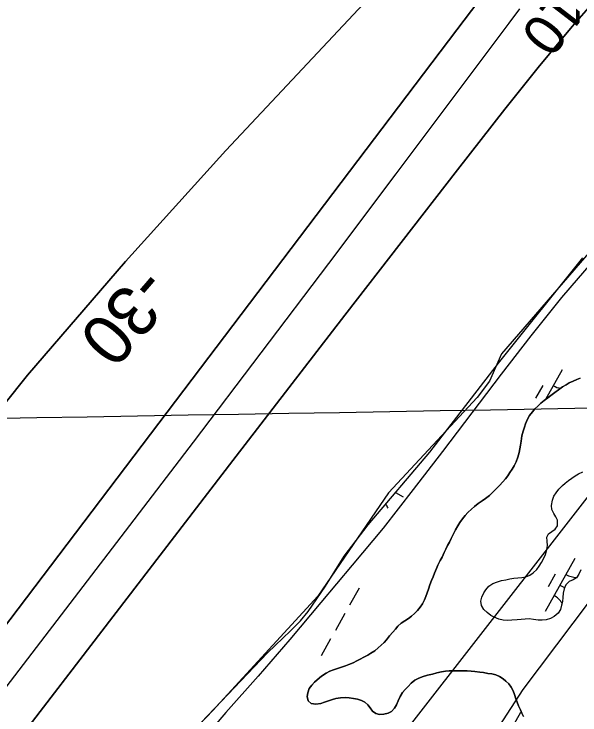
# Model space of a CAD drawing. Extents: x 3913936 to 3933962, y 195330 to 217741.
# Drawn here: x 3922187 to 3922654, y 199333 to 199912 of the extents above; entities that cross this region are included whole.
import ezdxf

# ---------------------------------------------------------------- set-up
doc = ezdxf.new("R2010")
doc.units = 0
for name, color, linetype in [('V-GRID-MAJR', 7, 'Continuous'), ('V-RIVR-EDGE', 7, 'Continuous'), ('V-RIVR-RANG', 7, 'Continuous'), ('V-RRAP-FSHR', 7, 'Continuous'), ('V-TOPO-DPTH', 7, 'Continuous'), ('V-TOPO-MINR', 7, 'Continuous'), ('V-TOPO-MINR-IDEN', 7, 'Continuous'), ('V-TOPO-SHOR', 7, 'Continuous'), ('V-UTIL-LINE', 7, 'Continuous'), ('V-WETL-SWMP', 7, 'Continuous')]:
    doc.layers.add(name, color=color, linetype=linetype)

msp = doc.modelspace()

# ---------------------------------------------------------------- linework, layer by layer
at = {"layer": 'V-GRID-MAJR'}
msp.add_spline([(3918580.26, 199515.41), (3920000.19, 199540.18), (3925326.04, 199633.54), (3926654.92, 199656.95)], degree=3, dxfattribs=at)
at = {"layer": 'V-RIVR-EDGE'}
msp.add_lwpolyline([(3922915.85, 200002.09), (3922760.82, 199830.21), (3922588.94, 199631.37), (3922578.83, 199608.9), (3922568.72, 199595.42), (3922495.7, 199516.78), (3922437.28, 199431.4), (3922350.78, 199337.04), (3922232.82, 199213.46), (3922129.47, 199055.06)], dxfattribs=at)
at = {"layer": 'V-RRAP-FSHR'}
msp.add_lwpolyline([(3922856.72, 199910.69), (3922828.81, 199882.43), (3922800.8, 199853.48), (3922772.41, 199825.3), (3922744.18, 199797.13), (3922715.63, 199768.95), (3922689.57, 199738.64), (3922664.23, 199707.86), (3922638.48, 199677.79), (3922612.93, 199646.3), (3922588.47, 199614.66), (3922564.3, 199582.79), (3922540.12, 199550.92), (3922515.95, 199519.51), (3922491.29, 199487.57), (3922465.58, 199456.93), (3922439.87, 199426.28), (3922414.17, 199395.64), (3922387.94, 199365.43), (3922361.51, 199335.42), (3922335.68, 199305.4)], dxfattribs=at)
at = {"layer": 'V-TOPO-DPTH'}
for points in [[(3923572.36, 200998.52), (3923503.91, 200907.2), (3923435.27, 200816.03), (3923326.2, 200671.67), (3923311.77, 200652.93), (3923297.12, 200634.37), (3923282.13, 200616.08), (3923266.93, 200597.97), (3923166.97, 200481.11), (3923101.22, 200405.05), (3923034.94, 200329.46), (3922967.87, 200254.57), (3922900.28, 200180.15), (3922705.27, 199967.65), (3922675.93, 199934.9), (3922647.14, 199901.69), (3922619.17, 199867.8), (3922591.73, 199833.44), (3922552.62, 199783.23), (3922506.1, 199723.37), (3922459.66, 199663.45), (3922413.34, 199603.44), (3922367.1, 199543.37), (3922084.4, 199175.27)], [(3922148.48, 199366.57), (3922552.04, 199898.75), (3922570.26, 199922.71), (3922588.51, 199946.64), (3922606.81, 199970.53), (3922625.15, 199994.39), (3922688.22, 200076.25), (3922736.83, 200138.24), (3922786.12, 200199.67), (3922836.45, 200260.25), (3922887.47, 200320.27), (3922938.76, 200380.07), (3922989.72, 200440.16), (3923040.17, 200500.67), (3923090.29, 200561.46), (3923185.73, 200678.2), (3923195.93, 200690.87), (3923206, 200703.64), (3923215.88, 200716.57), (3923225.63, 200729.59), (3923304.51, 200836.62), (3923353.97, 200902.94), (3923403.94, 200968.88)], [(3923403.94, 200968.88), (3923353.97, 200902.94), (3923304.51, 200836.62), (3923225.63, 200729.59), (3923215.88, 200716.57), (3923206, 200703.64), (3923195.93, 200690.87), (3923185.73, 200678.2), (3923090.29, 200561.46), (3923040.17, 200500.67), (3922989.72, 200440.16), (3922938.76, 200380.07), (3922887.47, 200320.27), (3922836.45, 200260.25), (3922786.12, 200199.67), (3922736.83, 200138.24), (3922688.22, 200076.25), (3922625.15, 199994.39), (3922606.81, 199970.53), (3922588.51, 199946.64), (3922570.26, 199922.71), (3922552.04, 199898.75), (3922148.48, 199366.57)], [(3922120.56, 199517.31), (3922197.86, 199613.84), (3922278.57, 199707.54), (3922361.53, 199799.36), (3922529.74, 199978.99)], [(3922529.74, 199978.99), (3922361.53, 199799.36), (3922278.57, 199707.54), (3922197.86, 199613.84), (3922120.56, 199517.31)]]:
    msp.add_lwpolyline(points, dxfattribs=at)
at = {"layer": 'V-TOPO-MINR'}
for points in [[(3922084.4, 199175.27), (3922367.1, 199543.37), (3922413.34, 199603.44), (3922459.66, 199663.45), (3922506.1, 199723.37), (3922552.62, 199783.23), (3922591.73, 199833.44), (3922619.17, 199867.8), (3922647.14, 199901.69), (3922675.93, 199934.9), (3922705.27, 199967.65), (3922900.28, 200180.15), (3922967.87, 200254.57), (3923034.94, 200329.46), (3923101.22, 200405.05), (3923166.97, 200481.11), (3923266.93, 200597.97), (3923282.13, 200616.08), (3923297.12, 200634.37), (3923311.77, 200652.93), (3923326.2, 200671.67), (3923435.27, 200816.03), (3923503.91, 200907.2), (3923572.36, 200998.52)], [(3922148.48, 199366.57), (3922552.04, 199898.75), (3922570.26, 199922.71), (3922588.51, 199946.64), (3922606.81, 199970.53), (3922625.15, 199994.39), (3922688.22, 200076.25), (3922736.83, 200138.24), (3922786.12, 200199.67), (3922836.45, 200260.25), (3922887.47, 200320.27), (3922938.76, 200380.07), (3922989.72, 200440.16), (3923040.17, 200500.67), (3923090.29, 200561.46), (3923185.73, 200678.2), (3923195.93, 200690.87), (3923206, 200703.64), (3923215.88, 200716.57), (3923225.63, 200729.59), (3923304.51, 200836.62), (3923353.97, 200902.94), (3923403.94, 200968.88)], [(3922120.56, 199517.31), (3922197.86, 199613.84), (3922278.57, 199707.54), (3922361.53, 199799.36), (3922529.74, 199978.99)], [(3922036.49, 199168.9), (3922278.56, 199485.01), (3922334.68, 199558.54), (3922390.63, 199632.19), (3922446.35, 199706.03), (3922501.91, 199779.98), (3922595.1, 199904.45), (3922603.96, 199916.25)]]:
    msp.add_lwpolyline(points, dxfattribs=at)
at = {"layer": 'V-TOPO-SHOR'}
for points in [[(3922523.75, 199425.15), (3922525.3, 199428.35), (3922526.41, 199431.21), (3922527.53, 199434.16), (3922528.56, 199437.1), (3922529.85, 199440.65), (3922531.14, 199444.2), (3922532.34, 199447.32), (3922533.46, 199450.26), (3922535.18, 199454.08), (3922536.46, 199457.02), (3922538.36, 199460.92), (3922539.82, 199463.69), (3922541.46, 199467.33), (3922542.92, 199470.1), (3922544.38, 199473.31), (3922545.84, 199475.99), (3922547.3, 199478.94), (3922549.03, 199482.23), (3922551, 199486.05), (3922552.81, 199489.34), (3922554.54, 199492.29), (3922556.69, 199495.23), (3922558.85, 199498.01), (3922561.17, 199500.52), (3922564.02, 199503.21), (3922566.61, 199505.47), (3922569.72, 199507.82), (3922572.83, 199509.99), (3922575.76, 199512.07), (3922578.87, 199514.59), (3922581.81, 199517.19), (3922584.57, 199519.97), (3922587.15, 199522.66), (3922590, 199525.78), (3922592.07, 199528.3), (3922594.05, 199530.81), (3922595.86, 199533.41), (3922597.67, 199536.18), (3922599.4, 199539.05), (3922600.94, 199542.25), (3922602.4, 199546.15), (3922603.43, 199549.87), (3922604.03, 199552.99), (3922604.54, 199556.11), (3922605.14, 199559.39), (3922605.73, 199563.63), (3922606.75, 199567.62), (3922607.7, 199570.82), (3922608.64, 199573.68), (3922610.28, 199577.4), (3922612.08, 199580.44), (3922614.33, 199583.56), (3922616.4, 199585.99), (3922618.81, 199588.33), (3922621.4, 199590.76), (3922624.16, 199592.93), (3922627.1, 199595.1), (3922629.52, 199597.1), (3922632.88, 199599.62), (3922635.91, 199601.7), (3922639.27, 199604.05), (3922642.12, 199605.78), (3922644.71, 199607.35), (3922648.08, 199608.92), (3922650.94, 199610.14), (3922653.79, 199611.27)], [(3922635.02, 199493.99), (3922633.81, 199496.75), (3922632.16, 199499.69), (3922630.51, 199502.79), (3922630.07, 199506.33), (3922630.92, 199510.57), (3922632.12, 199513.95), (3922634.01, 199516.8), (3922636.25, 199519.66), (3922639.18, 199522.61), (3922641.51, 199524.69), (3922644.09, 199526.85), (3922646.85, 199528.76), (3922649.53, 199530.58), (3922652.37, 199532.49), (3922655.91, 199534.06)], [(3922615.1, 199450.56), (3922618.03, 199453.42), (3922620.01, 199456.27), (3922621.81, 199459.22), (3922623.45, 199462.16), (3922625.17, 199465.79), (3922626.28, 199469.77), (3922626.7, 199473.14), (3922626.43, 199476.86), (3922626.34, 199480.05), (3922627.71, 199482.91), (3922630.3, 199484.65), (3922633.23, 199486.73), (3922635.04, 199489.41), (3922635.02, 199493.99)], [(3922654.24, 199453.17), (3922652.78, 199449.54), (3922650.8, 199446.51), (3922647.87, 199444.86), (3922644.67, 199443.55), (3922641.91, 199440.69), (3922640.45, 199437.49), (3922639.77, 199433.95), (3922639.44, 199430.23), (3922639.1, 199426.95), (3922638.5, 199423.92), (3922637.48, 199420.38), (3922635.58, 199417.26), (3922632.31, 199414.49), (3922629.29, 199412.83), (3922625.75, 199411.79), (3922622.38, 199411.52), (3922619.18, 199411.68), (3922615.29, 199412.19), (3922611.75, 199412.7), (3922608.29, 199412.52), (3922605.01, 199412.16), (3922601.73, 199411.72), (3922597.41, 199411.54), (3922594.21, 199411.27), (3922590.15, 199411.69), (3922586.69, 199412.37), (3922582.8, 199414), (3922580.03, 199415.38), (3922576.91, 199417.87), (3922574.4, 199420.37), (3922572.31, 199423.56), (3922571.87, 199427.28), (3922572.73, 199430.48), (3922574.36, 199434.03), (3922575.99, 199436.71), (3922578.32, 199439.65), (3922581.59, 199441.91), (3922585.48, 199443.21), (3922588.85, 199444.26), (3922592.56, 199444.96), (3922595.67, 199445.66), (3922598.95, 199446.11), (3922602.23, 199446.55), (3922605.6, 199446.82), (3922608.89, 199447.43), (3922612.25, 199448.73), (3922615.1, 199450.56)], [(3922607.07, 199331.94), (3922605.76, 199334.7), (3922604.46, 199337.64), (3922602.98, 199340.75), (3922601.76, 199343.78), (3922600.8, 199346.71), (3922599.49, 199350.17), (3922598.36, 199353.11), (3922596.88, 199356.22), (3922594.79, 199359.07), (3922592.45, 199361.23), (3922590.11, 199363.12), (3922587.07, 199365.1), (3922584.13, 199366.4), (3922580.84, 199367.17), (3922577.64, 199367.67), (3922574.09, 199368.27), (3922571.06, 199368.69), (3922566.91, 199369.29), (3922563.79, 199369.54), (3922560.41, 199369.7), (3922556.35, 199369.78), (3922552.54, 199369.68), (3922549.25, 199369.76), (3922545.71, 199369.66), (3922542.59, 199369.4), (3922539.22, 199368.86), (3922535.42, 199368.08), (3922531.96, 199367.11), (3922527.72, 199366.07), (3922523.4, 199364.75), (3922520.03, 199363.53), (3922517.26, 199362.06), (3922514.33, 199359.63), (3922511.74, 199356.94), (3922509.24, 199354.33), (3922507.08, 199351.82), (3922505.19, 199348.61), (3922503.55, 199345.06), (3922502.18, 199341.77), (3922500.46, 199338.82), (3922498.13, 199336.13), (3922495.27, 199334.83), (3922491.82, 199334.04), (3922488.18, 199333.77), (3922485.15, 199334.45), (3922482.29, 199336.43), (3922480.47, 199339.2), (3922478.56, 199341.7), (3922476.04, 199343.94), (3922473.36, 199345.32), (3922470.15, 199346.27), (3922466.86, 199346.86), (3922463.06, 199347.37), (3922459.77, 199347.62), (3922455.96, 199347.35), (3922452.24, 199346.91), (3922449.3, 199346.12), (3922446.1, 199345.07), (3922442.91, 199343.77), (3922439.79, 199342.81), (3922435.73, 199342.19), (3922431.83, 199342.78), (3922429.41, 199344.94), (3922428.53, 199348.49), (3922428.95, 199351.69), (3922430.24, 199355.15), (3922432.31, 199358.01), (3922434.55, 199360.27), (3922436.88, 199362.44), (3922440.34, 199365.21), (3922444.31, 199367.74), (3922447.25, 199369.39), (3922450.27, 199370.52), (3922453.56, 199371.66), (3922456.84, 199372.79), (3922460.13, 199373.84), (3922462.98, 199374.97), (3922466.35, 199376.45), (3922469.37, 199378.01), (3922472.31, 199379.41), (3922475.25, 199380.89), (3922478.44, 199382.63), (3922481.12, 199384.28), (3922484.32, 199386.28), (3922487.08, 199388.71), (3922489.67, 199391.05), (3922491.91, 199393.13), (3922494.07, 199395.47), (3922496.57, 199398.51), (3922499.16, 199401.54), (3922501.31, 199404.15), (3922503.29, 199406.49), (3922505.97, 199409.01), (3922508.99, 199410.92), (3922512.19, 199413), (3922514.52, 199414.91), (3922517.19, 199417.17), (3922519.44, 199419.51), (3922521.77, 199422.29), (3922523.75, 199425.15)]]:
    msp.add_lwpolyline(points, dxfattribs=at)
at = {"layer": 'V-UTIL-LINE'}
for points in [[(3922166.91, 198676.44), (3922606.64, 199354.27), (3923719.03, 200830.83), (3923718.13, 200956.52)], [(3922951.57, 199888.34), (3922069.47, 198754.87)]]:
    msp.add_lwpolyline(points, dxfattribs=at)
at = {"layer": 'V-WETL-SWMP'}
for p, q in [((3922586.49, 199623.64), (3922655.96, 199710.58)), ((3922529.77, 199550.29), (3922586.49, 199623.64)), ((3922638.9, 199618.16), (3922625.11, 199593.63)), ((3922648.08, 199608.92), (3922644.71, 199607.35)), ((3922650.94, 199610.14), (3922648.08, 199608.92)), ((3922653.79, 199611.27), (3922650.94, 199610.14)), ((3922622.87, 199605.38), (3922616.99, 199594.92)), ((3922639.27, 199604.05), (3922635.91, 199601.7)), ((3922642.12, 199605.78), (3922639.27, 199604.05)), ((3922644.71, 199607.35), (3922642.12, 199605.78)), ((3922626.65, 199596.37), (3922627.83, 199595.71)), ((3922629.52, 199597.1), (3922627.1, 199595.1)), ((3922632.88, 199599.62), (3922629.52, 199597.1)), ((3922635.91, 199601.7), (3922632.88, 199599.62)), ((3922621.4, 199590.76), (3922618.81, 199588.33)), ((3922624.16, 199592.93), (3922621.4, 199590.76)), ((3922627.1, 199595.1), (3922624.16, 199592.93)), ((3922616.4, 199585.99), (3922614.33, 199583.56)), ((3922618.81, 199588.33), (3922616.4, 199585.99)), ((3922612.08, 199580.44), (3922610.28, 199577.4)), ((3922614.33, 199583.56), (3922612.08, 199580.44)), ((3922608.64, 199573.68), (3922607.7, 199570.82)), ((3922610.28, 199577.4), (3922608.64, 199573.68)), ((3922606.76, 199567.62), (3922605.73, 199563.63)), ((3922607.7, 199570.82), (3922606.76, 199567.62)), ((3922605.73, 199563.63), (3922605.14, 199559.39)), ((3922604.54, 199556.1), (3922604.03, 199552.99)), ((3922605.14, 199559.39), (3922604.54, 199556.1)), ((3922478.83, 199490.13), (3922529.77, 199550.29)), ((3922603.43, 199549.87), (3922602.4, 199546.15)), ((3922604.03, 199552.99), (3922603.43, 199549.87)), ((3922602.4, 199546.15), (3922600.94, 199542.25)), ((3922599.4, 199539.05), (3922597.67, 199536.18)), ((3922600.94, 199542.25), (3922599.4, 199539.05)), ((3922595.86, 199533.41), (3922594.05, 199530.81)), ((3922597.67, 199536.18), (3922595.86, 199533.41)), ((3922592.07, 199528.3), (3922590, 199525.78)), ((3922594.05, 199530.81), (3922592.07, 199528.3)), ((3922587.16, 199522.66), (3922584.57, 199519.97)), ((3922590, 199525.78), (3922587.16, 199522.66)), ((3922501.42, 199516.81), (3922507.74, 199513.26)), ((3922581.81, 199517.19), (3922578.87, 199514.59)), ((3922584.57, 199519.97), (3922581.81, 199517.19)), ((3922572.83, 199509.99), (3922569.72, 199507.82)), ((3922575.76, 199512.07), (3922572.83, 199509.99)), ((3922578.87, 199514.59), (3922575.76, 199512.07)), ((3922566.61, 199505.47), (3922564.02, 199503.21)), ((3922569.72, 199507.82), (3922566.61, 199505.47)), ((3922558.85, 199498.01), (3922556.69, 199495.23)), ((3922561.17, 199500.52), (3922558.85, 199498.01)), ((3922564.02, 199503.21), (3922561.17, 199500.52)), ((3922554.54, 199492.29), (3922552.81, 199489.34)), ((3922556.69, 199495.23), (3922554.54, 199492.29)), ((3922459.15, 199464.51), (3922478.83, 199490.13)), ((3922551, 199486.05), (3922549.03, 199482.23)), ((3922552.81, 199489.34), (3922551, 199486.05)), ((3922549.03, 199482.23), (3922547.31, 199478.94)), ((3922545.84, 199476), (3922544.38, 199473.31)), ((3922547.31, 199478.94), (3922545.84, 199476)), ((3922542.92, 199470.1), (3922541.45, 199467.33)), ((3922544.38, 199473.31), (3922542.92, 199470.1)), ((3922443.73, 199439.69), (3922459.15, 199464.51)), ((3922539.82, 199463.69), (3922538.36, 199460.92)), ((3922541.45, 199467.33), (3922539.82, 199463.69)), ((3922538.36, 199460.92), (3922536.46, 199457.02)), ((3922649.3, 199462.37), (3922624.8, 199418.78)), ((3922535.18, 199454.08), (3922533.46, 199450.27)), ((3922536.46, 199457.02), (3922535.18, 199454.08)), ((3922532.34, 199447.32), (3922531.14, 199444.2)), ((3922533.46, 199450.27), (3922532.34, 199447.32)), ((3922633.26, 199449.58), (3922627.38, 199439.12)), ((3922529.85, 199440.65), (3922528.56, 199437.1)), ((3922531.14, 199444.2), (3922529.85, 199440.65)), ((3922637.05, 199440.57), (3922640.88, 199438.42)), ((3922429.46, 199418.74), (3922443.73, 199439.69)), ((3922471.35, 199437.89), (3922463.51, 199423.94)), ((3922527.53, 199434.16), (3922526.41, 199431.21)), ((3922528.56, 199437.1), (3922527.53, 199434.16)), ((3922525.3, 199428.35), (3922523.75, 199425.15)), ((3922526.41, 199431.21), (3922525.3, 199428.35)), ((3922523.75, 199425.15), (3922521.77, 199422.29)), ((3922422.9, 199410.97), (3922429.46, 199418.74)), ((3922459.59, 199416.97), (3922451.75, 199403.02)), ((3922517.2, 199417.17), (3922514.52, 199414.91)), ((3922519.44, 199419.51), (3922517.2, 199417.17)), ((3922521.77, 199422.29), (3922519.44, 199419.51)), ((3922414.79, 199402.82), (3922422.9, 199410.97)), ((3922508.99, 199410.92), (3922505.97, 199409.01)), ((3922512.19, 199413), (3922508.99, 199410.92)), ((3922514.52, 199414.91), (3922512.19, 199413)), ((3922503.29, 199406.49), (3922501.31, 199404.15)), ((3922505.97, 199409.01), (3922503.29, 199406.49)), ((3922395.86, 199384.57), (3922414.79, 199402.82)), ((3922499.16, 199401.55), (3922496.57, 199398.51)), ((3922501.31, 199404.15), (3922499.16, 199401.55)), ((3922447.83, 199396.05), (3922439.99, 199382.1)), ((3922494.07, 199395.47), (3922491.91, 199393.13)), ((3922496.57, 199398.51), (3922494.07, 199395.47)), ((3922487.08, 199388.71), (3922484.32, 199386.28)), ((3922489.67, 199391.05), (3922487.08, 199388.71)), ((3922491.91, 199393.13), (3922489.67, 199391.05)), ((3922341.03, 199327.1), (3922395.86, 199384.57)), ((3922478.44, 199382.63), (3922475.25, 199380.89)), ((3922481.12, 199384.28), (3922478.44, 199382.63)), ((3922484.32, 199386.28), (3922481.12, 199384.28)), ((3922466.35, 199376.45), (3922462.98, 199374.97)), ((3922469.37, 199378.01), (3922466.35, 199376.45)), ((3922472.31, 199379.41), (3922469.37, 199378.01)), ((3922475.25, 199380.89), (3922472.31, 199379.41)), ((3922450.27, 199370.52), (3922447.25, 199369.39)), ((3922453.56, 199371.65), (3922450.27, 199370.52)), ((3922456.84, 199372.79), (3922453.56, 199371.65)), ((3922460.13, 199373.84), (3922456.84, 199372.79)), ((3922462.98, 199374.97), (3922460.13, 199373.84)), ((3922440.34, 199365.21), (3922436.88, 199362.44)), ((3922444.31, 199367.74), (3922440.34, 199365.21)), ((3922447.25, 199369.39), (3922444.31, 199367.74)), ((3922520.03, 199363.53), (3922523.4, 199364.76)), ((3922523.4, 199364.76), (3922527.72, 199366.07)), ((3922527.72, 199366.07), (3922531.96, 199367.11)), ((3922531.96, 199367.11), (3922535.42, 199368.08)), ((3922535.42, 199368.08), (3922539.22, 199368.86)), ((3922539.22, 199368.86), (3922542.59, 199369.39)), ((3922542.59, 199369.39), (3922545.71, 199369.66)), ((3922545.71, 199369.66), (3922549.25, 199369.76)), ((3922549.25, 199369.76), (3922552.54, 199369.68)), ((3922552.54, 199369.68), (3922556.35, 199369.78)), ((3922556.35, 199369.78), (3922560.41, 199369.7)), ((3922560.41, 199369.7), (3922563.79, 199369.54)), ((3922563.79, 199369.54), (3922566.91, 199369.29)), ((3922566.91, 199369.29), (3922571.06, 199368.69)), ((3922571.06, 199368.69), (3922574.09, 199368.27)), ((3922574.09, 199368.27), (3922577.64, 199367.67)), ((3922577.64, 199367.67), (3922580.84, 199367.17)), ((3922580.84, 199367.17), (3922584.13, 199366.4)), ((3922584.13, 199366.4), (3922587.08, 199365.11)), ((3922587.08, 199365.11), (3922590.11, 199363.12)), ((3922434.55, 199360.27), (3922432.31, 199358.01)), ((3922436.88, 199362.44), (3922434.55, 199360.27)), ((3922511.74, 199356.94), (3922514.33, 199359.62)), ((3922514.33, 199359.62), (3922517.26, 199362.06)), ((3922517.26, 199362.06), (3922520.03, 199363.53)), ((3922590.11, 199363.12), (3922592.45, 199361.23)), ((3922592.45, 199361.23), (3922594.79, 199359.07)), ((3922594.79, 199359.07), (3922596.88, 199356.22)), ((3922430.24, 199355.15), (3922428.95, 199351.69)), ((3922432.31, 199358.01), (3922430.24, 199355.15)), ((3922507.08, 199351.82), (3922509.24, 199354.33)), ((3922509.24, 199354.33), (3922511.74, 199356.94)), ((3922596.88, 199356.22), (3922598.36, 199353.11)), ((3922598.36, 199353.11), (3922599.49, 199350.17)), ((3922428.95, 199351.69), (3922428.53, 199348.48)), ((3922428.53, 199348.48), (3922429.41, 199344.94)), ((3922452.24, 199346.91), (3922455.96, 199347.35)), ((3922455.96, 199347.35), (3922459.77, 199347.62)), ((3922459.77, 199347.62), (3922463.06, 199347.37)), ((3922463.06, 199347.37), (3922466.86, 199346.86)), ((3922503.55, 199345.06), (3922505.19, 199348.61)), ((3922505.19, 199348.61), (3922507.08, 199351.82)), ((3922599.49, 199350.17), (3922600.8, 199346.71)), ((3922429.41, 199344.94), (3922431.83, 199342.78)), ((3922431.83, 199342.78), (3922435.73, 199342.19)), ((3922435.73, 199342.19), (3922439.79, 199342.8)), ((3922439.79, 199342.8), (3922442.91, 199343.77)), ((3922442.91, 199343.77), (3922446.1, 199345.07)), ((3922446.1, 199345.07), (3922449.3, 199346.12)), ((3922449.3, 199346.12), (3922452.24, 199346.91)), ((3922466.86, 199346.86), (3922470.15, 199346.26)), ((3922470.15, 199346.26), (3922473.36, 199345.32)), ((3922473.36, 199345.32), (3922476.04, 199343.95)), ((3922476.04, 199343.95), (3922478.56, 199341.7)), ((3922478.56, 199341.7), (3922480.47, 199339.2)), ((3922500.46, 199338.82), (3922502.18, 199341.77)), ((3922502.18, 199341.77), (3922503.55, 199345.06)), ((3922600.8, 199346.71), (3922601.76, 199343.78)), ((3922601.76, 199343.78), (3922602.98, 199340.75)), ((3922480.47, 199339.2), (3922482.29, 199336.43)), ((3922482.29, 199336.43), (3922485.15, 199334.45)), ((3922495.27, 199334.83), (3922498.13, 199336.13)), ((3922498.13, 199336.13), (3922500.46, 199338.82)), ((3922602.98, 199340.75), (3922604.46, 199337.64)), ((3922604.46, 199337.64), (3922605.76, 199334.7)), ((3922485.15, 199334.45), (3922488.18, 199333.77)), ((3922488.18, 199333.77), (3922491.82, 199334.04)), ((3922491.82, 199334.04), (3922495.27, 199334.83)), ((3922604.59, 199335.46), (3922596.75, 199321.51)), ((3922605.76, 199334.7), (3922607.07, 199331.94))]:
    msp.add_line(p, q, dxfattribs=at)
for points in [[(3922615.1, 199450.56), (3922618.03, 199453.42), (3922620.01, 199456.27), (3922621.81, 199459.22), (3922623.45, 199462.16), (3922625.17, 199465.79), (3922626.28, 199469.77), (3922626.7, 199473.14), (3922626.43, 199476.86), (3922626.34, 199480.05), (3922627.71, 199482.91), (3922630.3, 199484.65), (3922633.23, 199486.73), (3922635.04, 199489.41), (3922635.02, 199493.99), (3922633.81, 199496.75), (3922632.16, 199499.69), (3922630.51, 199502.79), (3922630.06, 199506.33), (3922630.92, 199510.57), (3922632.12, 199513.95), (3922634.01, 199516.8), (3922636.25, 199519.66), (3922639.18, 199522.61), (3922641.51, 199524.69), (3922644.09, 199526.85), (3922646.85, 199528.76), (3922649.53, 199530.58), (3922652.37, 199532.49), (3922655.91, 199534.06)], [(3922654.24, 199453.17), (3922652.78, 199449.54), (3922650.8, 199446.51), (3922647.86, 199444.86), (3922644.67, 199443.55), (3922641.91, 199440.69), (3922640.45, 199437.49), (3922639.77, 199433.95), (3922639.44, 199430.23), (3922639.1, 199426.95), (3922638.5, 199423.92), (3922637.48, 199420.38), (3922635.58, 199417.26), (3922632.31, 199414.49), (3922629.29, 199412.83), (3922625.75, 199411.79), (3922622.38, 199411.52), (3922619.18, 199411.68), (3922615.29, 199412.19), (3922611.75, 199412.7), (3922608.29, 199412.52), (3922605.01, 199412.16), (3922601.73, 199411.72), (3922597.41, 199411.54), (3922594.21, 199411.27), (3922590.15, 199411.69), (3922586.69, 199412.37), (3922582.79, 199414), (3922580.03, 199415.38), (3922576.91, 199417.87), (3922574.4, 199420.37), (3922572.31, 199423.56), (3922571.87, 199427.28), (3922572.73, 199430.48)], [(3922572.73, 199430.48), (3922574.36, 199434.02), (3922575.99, 199436.71), (3922578.32, 199439.65), (3922581.59, 199441.91), (3922585.48, 199443.22), (3922588.85, 199444.26), (3922592.56, 199444.96), (3922595.67, 199445.66), (3922598.95, 199446.11), (3922602.23, 199446.55), (3922605.6, 199446.82), (3922608.89, 199447.43), (3922612.25, 199448.74), (3922615.1, 199450.56)]]:
    msp.add_lwpolyline(points, dxfattribs=at)
for centre, start, end in [((3922640.4, 199620.33), 239.88608, 261.07101), ((3922478.72, 199497.89), 19.88608, 32.94151), ((3922650.79, 199464.53), 239.88608, 270.88255), ((3922623.72, 199416.38), 31.09461, 61.42973)]:
    msp.add_arc(centre, 17.62, start, end, dxfattribs=at)

# ---------------------------------------------------------------- texts
at = {"layer": 'V-RIVR-RANG'}
msp.add_text('-10', height=33.5, rotation=232.44833, dxfattribs=at).set_placement((3922642.88, 199946.29))
at = {"layer": 'V-TOPO-MINR-IDEN'}
msp.add_text('-30', height=41.5, rotation=229.26362, dxfattribs=at).set_placement((3922290.64, 199705.66))

doc.saveas('drawing.dxf')
